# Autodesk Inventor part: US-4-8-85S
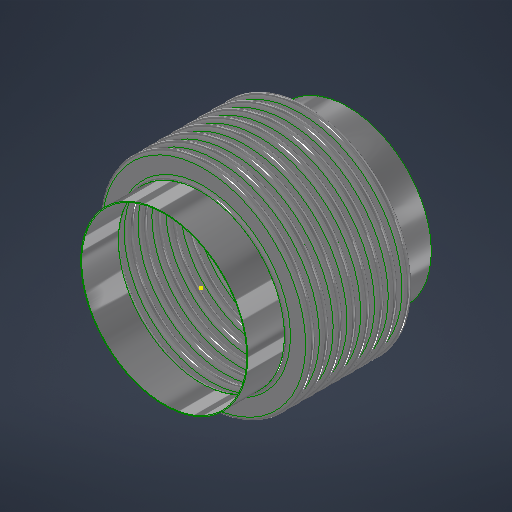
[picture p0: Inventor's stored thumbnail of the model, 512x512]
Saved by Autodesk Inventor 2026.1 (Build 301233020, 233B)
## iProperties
Category: 24 GA (0.024 THICK)
RuleStatus: InUse
Created: 2026-07
Part Number: US-4-8-85S
Project: =STOCK BELLOWS: <Stock Number><SFILL>
Material: ASTM A240-304
Description: =STOCK BELLOWS: <Stock Number>, <SID_> I.D., <SOD_> O.D., <SPLY_> PLY, <Category>, <SNET_CONS> CONS.<PITCH_><STANGENT_> TANGENT<SFILL>
Document SubType Name: Sheet Metal
Designer: LC
Stock Number: U.S-4-8-85S
Surface Area: 659.127 cm^2
Volume: 56.61 cm^3
Sheet Metal Rule: Default
Appearance: STAINLESS STEEL
NET_TUBE: 3.428
COUNTER: 1.500
PBAR: 1.214
PSET: 5.356
PLY: 2
CONS: 2
THK: 0.036
ID: 4.500
OD: 5.500
CONS_: 2
TANGENT: 0.500
PITCH: 0.375
BELLOWS_UPSET: 0.000
NET_CONS: 2
S_CONS: 0
Description_Units: 0
ID_M: 114.30 mm
OD_M: 139.70 mm
THK_M: 0.91 mm
ID_U: 4.500 in
OD_U: 5.500 in
THK_U: 0.036 in
TANGENT2: 0.500
d79: 1.000
d82: 1.000
d83: 26.000
d84: 24.000
d80: 2.571
d81: 10
SID: 2.375
SCONS_: 8
SPITCH: 0.250
SBELLOWS_UPSET: 0.000
SNET_CONS: 8
SS_CONS: 0
SCONS: 8
d174: 8
d177: 0.018
d178: 2.375
d179: 3.000
d180: 0.375
d181: 1.000
d182: 0.000
d190: 8
d191: 1
d192: 1
d193: 8
d194: 0
PART_NUMBER: U.S-4-8-85S
PRESSURE: 85
SIZE: 4.00
STANGENT_: 1.000
d214: 8
d217: 0.030
d218: 6.625
d219: 8.125
d220: 0.500
d221: 1.000
d222: 0.000
d230: 8
d231: 1
d232: 1
d233: 8
d234: 0
STANGENT: 4.000
SPLY_: 1
STHK_: 0.024
SID_: 4.500
SOD_: 5.750
SPITCH_: 0.375
STANGENT__: 1.000
SBELLOWS_UPSET_: 0.000
SDIFF_TAN: 1.000
TAN_TO_TAN: 0.750 in
d252: 2
d275: 2
d287: 0.050
d289: 0.500
d290: 0.000
d263: 2
d265: 1
d268: 2
d269: 0
d286: 2
d288: 1
d291: 2
d292: 0
SOD_NECK: 4 9/16
CFILL: .
SFILL: .
PITCH_: =, <SPITCH_> PITCH,
SREROLL: 0.750
MATTABLE: 20 GA (0.036 THICK)
MESH: ,
CSECT: 2
Author: LC
Keywords: 20 GA (0.036 THICK)
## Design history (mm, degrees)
sketch "Sketch2"
  geometry: L1 (0, -183.595)-(0, 600.956) reference; L2 (58.979, 0)-(57.15, 0); L3 (60.446, -1.467)-(66.554, -1.467); L4 (60.446, -3.296)-(66.554, -3.296); L5 (66.554, -8.058)-(60.446, -8.058); L6 (66.554, -6.229)-(60.446, -6.229); L7 (58.979, -9.525)-(57.15, -9.525); L8 (60.446, 0)-(60.446, -9.525); L9 (66.554, -4.762)-(69.85, -4.763); L10 (57.15, 0)-(57.15, -9.525); L11 (20.376, 102.841)-(20.376, 101.926); L12 (58.262, 488.877)-(58.262, 349.177); L13 (58.262, 479.352)-(58.262, 339.652); L14 (93.133, -58.817)-(93.133, -71.517); L15 (118.746, -66.401)-(118.746, -66.401); L16 (66.554, -6.229)-(66.554, -8.058); L17 (60.446, -6.229)-(60.446, -8.058); L18 (60.446, -7.144)-(66.554, -7.144); L19 (69.85, 0)-(69.85, -9.525); L20 (-66.554, -6.229)-(-66.554, -8.058); L21 (-66.554, -1.467)-(-60.446, -1.467); L22 (-66.554, -3.296)-(-60.446, -3.296); L23 (-60.446, -6.229)-(-66.554, -6.229); L24 (-66.554, -7.144)-(-60.446, -7.144); L25 (-60.446, -8.058)-(-66.554, -8.058); L26 (-60.446, -6.229)-(-60.446, -8.058); L27 (-57.15, -2.522)-(-57.15, -12.047); L28 (-60.446, -4.763)-(-57.15, -4.763); L29 (-66.554, 3.828)-(-66.554, -9.525); L30 (-68.021, 0)-(-69.85, 0); L31 (-69.85, 0)-(-69.85, -9.525); L32 (-68.021, -9.525)-(-69.85, -9.525); A1 r 1.467 centre (60.446, 0) between (58.979, 0) and (60.446, -1.467); A2 r 3.296 centre (60.446, 0) between (57.15, 0) and (60.446, -3.296); A3 r 3.296 centre (66.554, -4.762) between (66.554, -8.058) and (66.554, -1.467); A4 r 1.467 centre (66.554, -4.762) between (66.554, -6.229) and (66.554, -3.296); A5 r 1.467 centre (60.446, -9.525) between (60.446, -8.058) and (58.979, -9.525); A6 r 3.296 centre (60.446, -9.525) between (60.446, -6.229) and (57.15, -9.525); A7 r 2.381 centre (66.554, -4.762) between (66.554, -7.144) and (68.936, -4.762); A8 r 2.381 centre (60.446, -9.525) between (60.446, -7.144) and (58.064, -9.525); A9 r 1.467 centre (-66.554, -9.525) between (-66.554, -8.058) and (-68.021, -9.525); A10 r 1.467 centre (-60.446, -4.763) between (-60.446, -6.229) and (-60.446, -3.296); A11 r 2.381 centre (-60.446, -4.763) between (-60.446, -7.144) and (-58.064, -4.763); A12 r 3.296 centre (-60.446, -4.763) between (-60.446, -8.058) and (-60.446, -1.467); A13 r 2.381 centre (-66.554, -9.525) between (-66.554, -7.144) and (-68.936, -9.525); A14 r 3.296 centre (-66.554, -9.525) between (-66.554, -6.229) and (-69.85, -9.525); A15 r 1.467 centre (-66.554, 0) between (-68.021, 0) and (-66.554, -1.467); A16 r 3.296 centre (-66.554, 0) between (-69.85, 0) and (-66.554, -3.296); 10 further points
  constraints: 62 end point, 38 point on circle, 20 tangent, 16 centre point, 12 parallel, 9 midpoint, 7 vertical, 6 coincident, 6 concentric, 6 point on line, 4 equal radius, 4 perpendicular, 3 horizontal, 1 collinear, 1 horizontal alignment, 10 other
  dimensions: "THK" = 0.9144 distance of L11.start L11.end; "ID" = 114.3 distance of L11.end point (20.376, -12.374); "OD" = 139.7 distance of L12.start L12.end; "PITCH" = 9.525 distance of L12.start L13.start; "TANGENT" = 12.7 distance of L14.start L14.end; "BELLOWS_UPSET" = 0 distance of L15.start L15.end; "d43" = 114.3 diameter of L10 L1 (= ID); "d44" = 139.7 diameter of L9.end L1 (= OD); "d45" = 1.8288 distance between parallel lines of L5 L6 (computed from THK, PLY); "d46" = 3.29565 radius of A3 (computed from PITCH, THK, PLY); "UPSET_PITCH" = 9.525 distance of L2.end L7.end (derived); "SIDEWALL_ANGLE" = 0 deg angle of L3 L9 (derived); "CON_GAP" = 2.9337 distance of point (60.446, -6.229) point (60.446, -3.296) (derived); "TAN1" = 3.74046 dimension on A8 (derived); "TAN2" = 3.74046 dimension on A7 (derived); "LEG1" = 6.1087 distance of L18.start L18.end (derived); "d278" = 1.8288 distance between parallel lines of L25 L23 (derived); "d279" = 3.29565 radius of A12 (derived); "d280" = 9.525 distance of L30.end L31.end (derived); "d281" = 360 deg dimension on L21 L28 (derived); "d282" = 2.9337 distance of point (-66.554, -6.229) point (-66.554, -3.296) (derived); "d283" = 3.74046 dimension on A13 (derived); "d284" = 3.74046 dimension on A11 (derived); "d285" = 6.1087 distance of L24.start L24.end (derived); "d293" = 114.3 diameter of L27 L1 (derived); "d294" = 139.7 diameter of L31 L1 (derived)
  node "Sketch Rectangular Pattern1" dims "d31" = 25.4, "ID" = 114.3
  node "Sketch Rectangular Pattern2" dims "d39" = 25.4, "PITCH" = 9.525
revolve "CONS" stored, may be unused: angle "d48" = 90 deg
node "BELLOW MIDPLANE"
pattern_linear "Rectangular Pattern2" dims "d52" = 9.525 (= UPSET_PITCH)
sketch "Sketch5"
  geometry: C1 r 58.979 at (0, 0) reference; C2 r 57.15 at (0, 0) reference
extrude "TANGENT" new body sketch "Sketch5" distance "d53" = 12.7 (= TANGENT); taper "d54" = 0 deg
revolve "SAMETAN" stored, may be unused: angle "d65" = 90 deg
revolve "DIFFTAN" stored, may be unused: angle "d70" = 90 deg
sketch "Sketch9"
  geometry: L1 (58.391, 0)-(-58.391, 0) reference; L2 (0, -17.78)-(0, 17.78) reference; L3 (41.708, 0)-(-41.708, 0); L4 (41.708, -11.906)-(41.708, 11.906); L5 (29.008, -11.906)-(29.008, 11.906); L6 (15.418, 11.906)-(15.418, -11.906); L7 (-29.008, -11.906)-(-29.008, 11.906); L8 (-41.708, -11.906)-(-41.708, 11.906); L9 (40.914, -11.906)-(40.914, 11.906); L10 (41.708, -11.906)-(40.914, -11.906); L11 (41.708, 11.906)-(40.914, 11.906); L12 (15.815, 11.906)-(15.022, 11.906); L13 (15.022, 11.906)-(15.022, -11.906); L14 (15.022, -11.906)-(15.815, -11.906); L15 (15.815, -11.906)-(15.815, 11.906); L16 (-15.815, 11.906)-(-15.815, -11.906); L17 (-15.418, 11.906)-(-15.418, -11.906); L18 (-15.815, -11.906)-(-15.022, -11.906); L19 (-15.022, -11.906)-(-15.022, 11.906); L20 (-15.022, 11.906)-(-15.815, 11.906); L21 (-41.708, -11.906)-(-40.914, -11.906); L22 (-40.914, -11.906)-(-40.914, 11.906); L23 (-40.914, 11.906)-(-41.708, 11.906); L24 (-41.708, 11.906)-(-41.708, -11.906); L25 (41.708, -0.397)-(-41.708, -0.397); L26 (-41.708, -0.397)-(-41.708, 0.397); L27 (-41.708, 0.397)-(41.708, 0.397); L28 (41.708, 0.397)-(41.708, -0.397); L29 (-41.708, 11.906)-(41.708, 11.906); L30 (41.708, 11.906)-(41.708, 12.7); L31 (41.708, 12.7)-(-41.708, 12.7); L32 (-41.708, 12.7)-(-41.708, 11.906); L33 (41.708, -11.906)-(-41.708, -11.906); L34 (-41.708, -11.906)-(-41.708, -12.7); L35 (-41.708, -12.7)-(41.708, -12.7); L36 (41.708, -12.7)-(41.708, -11.906); 30 further points
  constraints: 68 end point, 13 midpoint, 13 parallel, 8 horizontal, 7 perpendicular, 6 equal length, 3 point on line, 2 vertical, 14 other
  dimensions: "d115" = 23.8125 distance of L4.start L4.end (derived); "d116" = 12.7 distance between parallel lines of L4 L5 (derived); "d117" = 13.58962 distance between parallel lines of L5 L6 (derived); "d125" = 44.42645 distance between parallel lines of L7 L6 (derived); "d127" = 12.7 distance between parallel lines of L8 L7 (derived); "d128" = 26.28962 distance between parallel lines of L6 L4 (derived); "d130" = 83.41607 distance between parallel lines of L8 L4 (derived); "RULER_THK" = 0.79375 distance between parallel lines of L4 L9; "d135" = 0.79375 distance of L13.end L14.end (derived); "d138" = 30.83684 distance of L13.end L16.end (derived); "d143" = 0.79375 distance of L22.end L8.end (derived); "d144" = 0.79375 distance between parallel lines of L27 L25 (derived)
extrude "RULER" join sketch "Sketch9" distance "d149" = 0.79375 (derived); taper "d150" = 0 deg
extrude "BARS" join sketch "Sketch9" distance "d151" = 0.79375 (derived); taper "d152" = 0 deg
pattern_linear "Rectangular Pattern4" dims "d155" = 30.83684 (derived)
sketch "Sketch13"
  geometry: L1 (93.149, -52.467)-(93.149, -77.867); L2 (57.76, 0)-(57.15, 0); L3 (57.76, -9.525)-(57.15, -9.525); L4 (70.339, -7.449)-(59.836, -7.449); L5 (70.339, -6.839)-(59.836, -6.839); L6 (70.339, -4.763)-(73.025, -4.763); L7 (59.836, -2.076)-(70.339, -2.076); L8 (59.836, 0)-(59.836, -9.525); L9 (57.15, 0)-(57.15, -9.525); L10 (58.254, -350.381)-(58.254, -496.431); L11 (58.254, -359.906)-(58.254, -505.956); L12 (58.254, -378.956)-(58.254, -525.006); L13 (58.254, -388.481)-(58.254, -534.531); L14 (58.254, -398.006)-(58.254, -544.056); L15 (58.254, -407.531)-(58.254, -553.581); L16 (58.254, -417.056)-(58.254, -563.106); L17 (58.254, -369.431)-(58.254, -515.481); L18 (20.376, 102.536)-(20.376, 101.926); L19 (59.836, -2.686)-(70.339, -2.686); L20 (0, -670.834)-(0, 231.431) reference; L21 (-23.752, 0)-(142.514, 0) reference; A1 r 2.076 centre (59.836, 0) between (57.76, 0) and (59.836, -2.076); A2 r 2.076 centre (59.836, -9.525) between (59.836, -7.449) and (57.76, -9.525); A3 r 2.686 centre (59.836, -9.525) between (59.836, -6.839) and (57.15, -9.525); A4 r 2.076 centre (70.339, -4.763) between (70.339, -6.839) and (70.339, -2.686); A5 r 2.686 centre (70.339, -4.763) between (70.339, -7.449) and (70.339, -2.076); A6 r 2.686 centre (59.836, 0) between (57.15, 0) and (59.836, -2.686); 6 further points; 1 other entity
  constraints: 38 end point, 15 point on circle, 9 tangent, 6 centre point, 6 parallel, 5 vertical alignment, 4 point on line, 4 vertical, 3 coincident, 3 concentric, 2 collinear, 2 equal radius, 1 horizontal, 1 perpendicular, 23 other
  dimensions: "SBELLOWS_UPSET_" = 0 distance of point (118.762, -66.401) point (118.762, -66.401); "STOTAL_THK_BELLOW__" = 0.6096 distance between parallel lines of L4 L5 (derived); "d224" = 2.68605 radius of A5 (derived); "d225" = 9.525 distance of L2.end L3.end (derived); "SSIDEWALL_ANGLE_" = 0 deg angle of L7 L6 (derived); "SSCON_GAP_" = 4.1529 distance of point (59.836, -6.839) point (59.836, -2.686) (derived); "d235" = 114.3 diameter of L9 L20 (derived); "d236" = 146.05 diameter of L6.end L20 (derived)
  node "Sketch Rectangular Pattern4" dims "d228" = 25.4
  node "Sketch Rectangular Pattern5" dims "d229" = 25.4
revolve "SBELLOW" stored, may be unused: angle "d197" = 90 deg
pattern_linear "Rectangular Pattern5" dims "d204" = 9.525 (derived)
revolve "STANGENT" stored, may be unused: angle "d240" = 90 deg
revolve "SSAMETAN" stored, may be unused: angle "d241" = 90 deg
revolve "SDIFFTAN" stored, may be unused: angle "d246" = 90 deg
revolve "INVCON" stored, may be unused: angle "d295" = 90 deg
pattern_linear "Rectangular Pattern6" dims "d298" = 9.525 (derived)
revolve "INVTANGENT" stored, may be unused: angle "d302" = 90 deg
revolve "INVSAMETAN" stored, may be unused: angle "d307" = 90 deg
revolve "INVDIFFTAN" stored, may be unused: angle "d312" = 90 deg
sketch "ID BELLOW MOUNT CALC"
  geometry: L1 (44.45, 0)-(38.1, 0); L2 (38.1, 0)-(38.1, 12.7); L3 (38.1, 12.7)-(44.45, 12.7); L4 (44.45, 12.7)-(44.45, 0); L5 (36.513, 12.7)-(34.684, 12.7); L6 (34.684, 12.7)-(34.684, 0); L7 (34.684, 0)-(36.513, 0); L8 (36.513, 0)-(36.513, 12.7); L9 (0, -2.54)-(0, 15.24) reference; L10 (-8.89, 0)-(53.34, 0) reference; 1 further point
  constraints: 16 end point, 5 parallel, 2 collinear, 2 horizontal, 2 perpendicular
  dimensions: "d314" = 12.7 distance of L5.end L6.end (derived); "d315" = 1.8288 distance of L5.start L5.end (derived); "IG" = 1.5875 distance between parallel lines of L2 L8; "PIPE_OD" = 88.9 diameter of L4 L9; "PIPE_WALL" = 6.35 distance of L2.end L3.end; "ID_MT_BELLOW" = 69.3674 diameter of L6 L9 (derived)
revolve "CFILL" stored, may be unused: angle "d320" = 90 deg
pattern_linear "Rectangular Pattern7" dims "d323" = 9.525 (derived)
revolve "SFILL" stored, may be unused: angle "d324" = 90 deg
pattern_linear "Rectangular Pattern8" dims "d327" = 9.525 (derived)
node "STOCK BELLOW MIDPLANE"
sketch "Sketch21"
  geometry: L1 (0, -100.013)-(0, 100.013) reference; L2 (-100.013, 0)-(100.013, 0) reference; L3 (-0.099, 71.437)-(0.099, 71.437); L4 (0.099, 71.437)-(0.099, 55.562); L5 (0.099, 55.562)-(-0.099, 55.562); L6 (-0.099, 55.562)-(-0.099, 71.437); C1 r 55.562 at (0, 0); C2 r 71.437 at (0, 0); 3 further points
  constraints: 8 end point, 2 centre point, 2 coincident, 2 parallel, 2 tangent, 1 horizontal, 1 perpendicular, 1 other
  dimensions: "d329" = 111.125 diameter of C1 (derived); "d330" = 142.875 diameter of C2 (derived); "d331" = 0.19844 distance of L3.start L3.end
extrude "CLAMSHELL" cut sketch "Sketch21" extent not by distance; stored distance "d332" = 0; taper "d333" = 0 deg
pattern_circular "Circular Pattern1" dims angle "d335" = 180 deg (derived)
node "BELLOW"
sketch "Sketch6"
  geometry: L1 (-19.05, 58.979)-(-6.35, 58.979); L2 (-6.35, 58.979)-(-6.35, 57.15); L3 (-6.35, 57.15)-(-19.05, 57.15); L4 (-19.05, 57.15)-(-19.05, 58.979); L5 (2.54, 0)-(-59.69, 0) reference; L6 (-38.1, -108.388)-(-38.1, 156.601) reference; 1 further point
  constraints: 8 end point, 2 parallel, 1 horizontal, 1 perpendicular
  dimensions: "d61" = 12.7 distance of L2.end L3.end (derived); "d62" = 1.8288 distance of L1.end L2.end (derived); "d63" = 114.3 diameter of L3 L5 (derived); "d64" = 19.05 distance between parallel lines of L4 L6 (derived)
sketch "Sketch12"
  geometry: 1 further point
sketch "Sketch14"
  geometry: L1 (-25.4, 57.76)-(0, 57.76); L2 (0, 57.76)-(0, 57.15); L3 (0, 57.15)-(-25.4, 57.15); L4 (-25.4, 57.15)-(-25.4, 57.76); L5 (5.08, 0)-(-30.48, 0) reference; L6 (0, -9.012)-(0, 54.072) reference; 1 further point
  constraints: 8 end point, 2 parallel, 1 collinear, 1 horizontal, 1 perpendicular
  dimensions: "d237" = 0.6096 distance of L3.end L1.start (derived); "d238" = 114.3 diameter of L3 L5 (derived); "d239" = 25.4 distance of L1.start L1.end (derived); "SOD_NECK" = 115.5192 diameter of L1 L5 (derived)
sketch "Sketch15"
  geometry: L1 (-9.012, 0)-(54.072, 0) reference; L2 (57.15, -76.2)-(57.76, -76.2); L3 (57.76, -76.2)-(57.76, -101.6); L4 (57.76, -101.6)-(57.15, -101.6); L5 (57.15, -101.6)-(57.15, -76.2); L6 (0, -124.46)-(0, 35.56) reference; 1 further point
  constraints: 8 end point, 2 parallel, 1 horizontal, 1 perpendicular
  dimensions: "d205" = 25.4 distance of L4.end L2.start (derived); "d206" = 0.6096 distance of L3.end L4.end (derived); "d207" = 114.3 diameter of L5 L6 (derived); "d208" = 76.2 distance between parallel lines of L1 L2 (derived)
node "TANGENT_"
node "SAME_TAN"
sketch "Sketch8"
  geometry: L1 (58.979, -19.05)-(57.15, -19.05); L2 (57.15, -19.05)-(57.15, -31.75); L3 (57.15, -31.75)-(58.979, -31.75); L4 (58.979, -31.75)-(58.979, -19.05); L5 (0, -40.64)-(0, 21.59) reference; L6 (-108.388, 0)-(156.601, 0) reference; 1 further point
  constraints: 8 end point, 2 parallel, 1 horizontal, 1 perpendicular
  dimensions: "d66" = 114.3 diameter of L2 L5 (derived); "TOTAL_THK_BELLOW" = 1.8288 distance of L2.end L3.end (derived); "d68" = 19.05 distance between parallel lines of L1 L6 (derived); "d69" = 12.7 distance of L1.end L2.end (derived)
node "DIFF_TAN"
node "Sketch Rectangular Pattern3" dims "d138" = 30.83684 (derived), "d141" = 25.4
node "SBELLOW_"
node "STANGENT_"
node "SSAME_TAN"
sketch "Sketch16"
  geometry: L1 (57.76, -76.2)-(57.15, -76.2); L2 (57.15, -76.2)-(57.15, -101.6); L3 (57.15, -101.6)-(57.76, -101.6); L4 (57.76, -101.6)-(57.76, -76.2); L5 (0, -124.46)-(0, 35.56) reference; L6 (-9.012, 0)-(54.072, 0) reference; 1 further point
  constraints: 8 end point, 2 parallel, 1 horizontal, 1 perpendicular
  dimensions: "SDIFF_TAN" = 25.4 distance of L3.end L1.start; "d243" = 0.6096 distance of L2.end L3.end (derived); "d244" = 76.2 distance between parallel lines of L1 L6 (derived); "d245" = 114.3 diameter of L2 L5 (derived)
node "SDIFF_TAN"
body "Solid15"
sketch "Sketch17"
  geometry: L1 (69.85, 12.7)-(68.021, 12.7); L2 (68.021, 12.7)-(68.021, 0); L3 (68.021, 0)-(69.85, 0); L4 (69.85, 0)-(69.85, 12.7); L5 (0, -2.54)-(0, 15.24) reference; L6 (-13.97, 0)-(83.82, 0) reference; 2 further points
  constraints: 8 end point, 2 parallel, 1 horizontal, 1 midpoint, 1 perpendicular, 1 point on line
  dimensions: "INVTANGENT" = 12.7 distance of L3.end L1.start (derived); "d300" = 1.8288 distance of L1.start L1.end (derived); "d301" = 139.7 diameter of L4 L5 (derived)
body "Solid16"
sketch "Sketch18"
  geometry: L1 (69.85, -19.05)-(68.021, -19.05); L2 (68.021, -19.05)-(68.021, -31.75); L3 (68.021, -31.75)-(69.85, -31.75); L4 (69.85, -31.75)-(69.85, -19.05); L5 (-13.97, 0)-(83.82, 0) reference; L6 (0, -40.64)-(0, 21.59) reference; 1 further point
  constraints: 8 end point, 2 parallel, 1 horizontal, 1 perpendicular
  dimensions: "d303" = 19.05 distance between parallel lines of L1 L5 (derived); "d304" = 12.7 distance of L3.end L1.start (derived); "d305" = 1.8288 distance of L2.end L3.end (derived); "d306" = 139.7 diameter of L4 L6 (derived)
body "Solid17"
sketch "Sketch19"
  geometry: L1 (69.85, -19.05)-(68.021, -19.05); L2 (68.021, -19.05)-(68.021, -31.75); L3 (68.021, -31.75)-(69.85, -31.75); L4 (69.85, -31.75)-(69.85, -19.05); L5 (0, -40.64)-(0, 21.59) reference; L6 (-13.97, 0)-(83.82, 0) reference; 1 further point
  constraints: 8 end point, 2 parallel, 1 horizontal, 1 perpendicular
  dimensions: "d308" = 12.7 distance of L1.end L2.end (derived); "d309" = 139.7 diameter of L4 L5 (derived); "d310" = 1.8288 distance of L2.end L3.end (derived); "d311" = 19.05 distance between parallel lines of L1 L6 (derived)
body "Solid18"
body "Solid19"
body "Solid20"
other parameters: "BMPL" = -38.1, "PSET" = 136.0424 (computed from OD, THK, PLY) [user parameter], "PBAR" = 30.83684 (= 0.570796 x PITCH + OD - ID) [user parameter; used in 1 equation term], "COUNTER" = 15 [user parameter], "NET_TUBE" = 87.07367 (computed from CONS_, PBAR, TANGENT) [user parameter], "S_CONS" = 0 [user parameter; used in 1 equation term], "ID_M" = 114.3 (= ID) [user parameter], "OD_M" = 139.7 (= OD) [user parameter], "THK_M" = 0.9144 (= THK) [user parameter], "ID_U" = 114.3 (= ID) [user parameter], "OD_U" = 139.7 (= OD) [user parameter], "THK_U" = 0.9144 (= THK) [user parameter], "D_UNITS" = 0 [user parameter], "TANGENT2" = 12.7 [user parameter], "TAN_TO_TAN" = 19.05 [user parameter], "OD_NECK" = 117.9576 [user parameter], "d79" = 25.4, "d80" = 65.29823 [user parameter], "d82" = 25.4, "d83" = 660.4, "d84" = 609.6, "sa_0" = 4, "FRAME_THK" = 0.79375 [user parameter], "CON_FLAT" = 13.58962 [user parameter], "SID" = 60.325 [user parameter], "SPITCH" = 6.35 [user parameter], "STANGENT_" = 25.4 [user parameter], "SBELLOWS_UPSET" = 0 [user parameter], "SS_CONS" = 0 [user parameter], "STAN_TO_TAN_" = 76.2 [user parameter], "d100" = 0.6096 [user parameter], "d191" = 25.4 [user parameter], "d194" = 0 [user parameter], "STANGENT" = 101.6 [user parameter], "d234" = 0 [user parameter], "SUPSET_PITCH_" = 9.525 [user parameter], "d269" = 0 [user parameter], "d287" = 1.27, "d289" = 12.7, "d290" = 0, "d292" = 0 [user parameter], "Thickness" = 3.048 (derived), "KFactor" = 4.4, "BendRadius" = 3.048 (derived), "BendReliefWidth" = 3.048 (derived), "BendReliefDepth" = 1.524 (derived), "CornerReliefSize" = 12.192 (derived), "SeamGap" = 0.00508, "MinimumRemnant" = 6.096 (derived), "TransitionRadius" = 3.048 (derived), "JacobiRadiusSize" = 3.048 (derived), "GapSize" = 3.048 (derived), "SREROLL" = 19.05 [user parameter], "CUR_STK_PITCH" = 9.525 [user parameter], "d328" = -38.1 (derived), "CSECTDEG" = 180 deg [user parameter]
